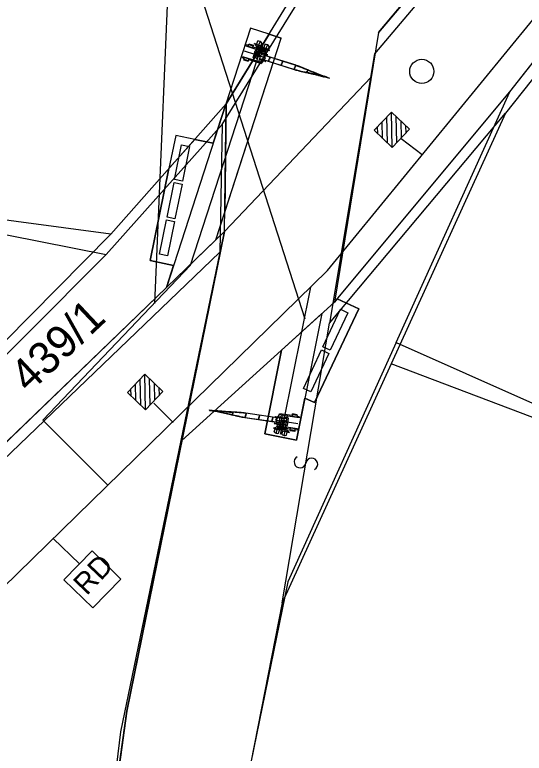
# Model space of a CAD drawing. Extents: x -678683 to -677755, y -1006946 to -1005971.
# Drawn here: x -678295.9 to -678264.31, y -1006533.89 to -1006488.07 of the extents above; entities that cross this region are included whole.
import ezdxf

# ---------------------------------------------------------------- set-up
doc = ezdxf.new("R2010")
doc.units = 0
for name, color, linetype in [('Default', 7, 'Continuous'), ('I_2_4_předběžný_vykres - Dočasný zábor - do 1 roku', 7, 'Continuous'), ('I_2_4_předběžný_vykres - Dočasný zábor - do 1 roku - ZPF', 7, 'Continuous'), ('I_2_4_předběžný_vykres - SŽDC', 7, 'Continuous'), ('I_2_4_předběžný_vykres - Trvalý zábor', 7, 'Continuous'), ('I_2_4_předběžný_vykres - VBř', 7, 'Continuous'), ('kilometráž - Vrstva 7', 7, 'Continuous'), ('koor - OSY', 7, 'Continuous'), ('koor - SSZT_nové', 7, 'Continuous'), ('MapaKN - Mladejov+Strelec_dosavani+nova_situace - Vrstva 11', 7, 'Continuous'), ('MapaKN - Mladejov+Strelec_dosavani+nova_situace - Vrstva 18', 7, 'Continuous'), ('MapaKN - původní vrstava 1', 7, 'Continuous'), ('popis', 7, 'Continuous')]:
    doc.layers.add(name, color=color, linetype=linetype)

# ---------------------------------------------------------------- blocks, each defined once
blk = doc.blocks.new('AZD97_VYSTRAZNIK')
at = {"layer": 'Default'}
for p, q in [((-34, -7.5), (-24, 8)), ((-24, 8), (0, 8)), ((-20, 2), (0, 2)), ((24, 8), (0, 8)), ((20, 2), (0, 2)), ((34, -7.5), (24, 8)), ((0, -7.5), (-40, -7.5)), ((-40, -7.5), (-40, -8)), ((0, -8), (-40, -8)), ((-36.9, -7.5), (-36.9, -3)), ((-36.9, -3), (-31.1, -3)), ((-34, -8), (-34, -9.5)), ((-34, -9.5), (-20, -9.5)), ((-31.5, -25.2), (-31.5, -9.5)), ((-20, -2), (0, -2)), ((-6, -9.5), (-20, -9.5)), ((-8.5, -25.2), (-8.5, -9.5)), ((-6, -8), (-6, -9.5)), ((20, -2), (0, -2)), ((0, -7.5), (40, -7.5)), ((0, -8), (40, -8)), ((6, -8), (6, -9.5)), ((6, -9.5), (20, -9.5)), ((8.5, -25.2), (8.5, -9.5)), ((34, -9.5), (20, -9.5)), ((36.9, -3), (31.1, -3)), ((31.5, -25.2), (31.5, -9.5)), ((34, -8), (34, -9.5)), ((36.9, -7.5), (36.9, -3)), ((40, -7.5), (40, -8))]:
    blk.add_line(p, q, dxfattribs=at)
for centre in [(-20, 0), (20, 0)]:
    blk.add_circle(centre, 2, dxfattribs=at)
for centre, start, end in [((-20, -9.5), 233.8612, 270), ((-20, -9.5), 270, 306.1388), ((20, -9.5), 233.8612, 270), ((20, -9.5), 270, 306.1388)]:
    blk.add_arc(centre, 19.5, start, end, dxfattribs=at)
at = {"layer": 'koor - OSY'}
for p, q in [((-24.8, 0), (25.7, 0)), ((-20, -29), (-20, 8)), ((0, 8), (0, -29.7)), ((20, -29), (20, 8))]:
    blk.add_line(p, q, dxfattribs=at)
blk = doc.blocks.new('AZD97_DRZAK')
at = {"layer": 'Default'}
for p, q in [((-4, -5.3), (-4, -38.3)), ((-0.7, -7.4), (-0.7, -6.6)), ((0.6, -7.4), (0.6, -6.6)), ((4, -5.3), (4, -38.3))]:
    blk.add_line(p, q, dxfattribs=at)
for centre, radius, start, end in [((0, 0), 6.65, 233.0223, 306.9777), ((0, 0), 7.5, 237.769, 270), ((0, 0), 7.5, 270, 302.231), ((0, -38.3), 4, 180, 0)]:
    blk.add_arc(centre, radius, start, end, dxfattribs=at)
at = {"layer": 'koor - OSY'}
for p, q in [((0, 6.6), (0, -42.3)), ((-6.7, 0), (6.6, 0)), ((-4, -38.3), (4, -38.3))]:
    blk.add_line(p, q, dxfattribs=at)
blk = doc.blocks.new('AZD99_KŘÍDLA')
at = {"layer": 'Default'}
for p, q in [((47, 47.5), (47, 52.5)), ((77, 52.5), (47, 52.5)), ((77, 47.5), (47, 47.5)), ((47, 47.5), (47, 36.5)), ((77, 47.5), (77, 52.5)), ((77, 47.5), (77, 36.5)), ((-56, 22), (-16, 22)), ((-56, 22), (-56, 20)), ((-56, 20), (-16, 20)), ((-46, 0), (-34, 42)), ((-46, 0), (-34, -42)), ((91, 34.5), (-36.2, 34.5)), ((47, 42), (-34, 42)), ((-16, 42), (-16, 0)), ((-16, -42), (-16, 0)), ((77, 36.5), (47, 36.5)), ((91, 42), (77, 42)), ((91, 42), (91, 34.5)), ((-56, -20), (-16, -20)), ((-56, -22), (-56, -20)), ((-56, -22), (-16, -22)), ((91, -34.5), (-36.2, -34.5)), ((47, -42), (-34, -42)), ((77, -36.5), (47, -36.5)), ((47, -47.5), (47, -36.5)), ((77, -47.5), (77, -36.5)), ((91, -42), (77, -42)), ((91, -42), (91, -34.5)), ((77, -47.5), (47, -47.5)), ((47, -47.5), (47, -52.5)), ((77, -52.5), (47, -52.5)), ((77, -47.5), (77, -52.5))]:
    blk.add_line(p, q, dxfattribs=at)
at = {"layer": 'koor - OSY'}
for p, q in [((-46, 0), (89, 0)), ((0, 21.9), (0, -22.2)), ((16, 42), (16, -42))]:
    blk.add_line(p, q, dxfattribs=at)

msp = doc.modelspace()

# ---------------------------------------------------------------- linework, layer by layer
at = {"layer": 'I_2_4_předběžný_vykres - Dočasný zábor - do 1 roku'}
for p, q in [((-678280.139, -1006489.272), (-678282.79, -1006493.59)), ((-678279.381, -1006489.517), (-678280.139, -1006489.272)), ((-678283.435, -1006502.026), (-678279.381, -1006489.517)), ((-678282.884, -1006500.325), (-678279.381, -1006489.517)), ((-678282.811, -1006493.613), (-678283.595, -1006496.033)), ((-678282.79, -1006493.59), (-678282.884, -1006500.325)), ((-678282.884, -1006500.325), (-678282.79, -1006493.59)), ((-678282.79, -1006493.59), (-678282.811, -1006493.613)), ((-678284.743, -1006495.797), (-678286.341, -1006497.603)), ((-678283.595, -1006496.033), (-678284.743, -1006495.797)), ((-678283.435, -1006502.026), (-678282.884, -1006500.325)), ((-678286.495, -1006504.981), (-678283.435, -1006502.026)), ((-678286.053, -1006503.616), (-678286.495, -1006504.981)), ((-678276.08, -1006505.89), (-678279.356, -1006508.868)), ((-678275.913, -1006505.69), (-678276.08, -1006505.89)), ((-678278.442, -1006514.466), (-678277.916, -1006511.854)), ((-678278.442, -1006514.466), (-678277.916, -1006511.854)), ((-678277.916, -1006511.854), (-678277.328, -1006512.133))]:
    msp.add_line(p, q, dxfattribs=at)
for points in [[(-678280.139, -1006489.272), (-678279.381, -1006489.517)], [(-678283.595, -1006496.033), (-678282.811, -1006493.613)], [(-678284.743, -1006495.797), (-678283.595, -1006496.033)], [(-678286.053, -1006503.616), (-678287.515, -1006503.316), (-678286.341, -1006497.603)], [(-678286.341, -1006497.603), (-678287.515, -1006503.316), (-678286.053, -1006503.616)], [(-678286.495, -1006504.981), (-678286.053, -1006503.616)], [(-678275.913, -1006505.69), (-678274.577, -1006506.322), (-678277.328, -1006512.133)], [(-678277.328, -1006512.133), (-678274.577, -1006506.322), (-678275.913, -1006505.69)], [(-678278.442, -1006514.466), (-678280.402, -1006514.072), (-678279.356, -1006508.868)], [(-678279.356, -1006508.868), (-678280.402, -1006514.072), (-678278.442, -1006514.466)], [(-678277.328, -1006512.133), (-678277.916, -1006511.854)]]:
    msp.add_lwpolyline(points, dxfattribs=at)
at = {"layer": 'I_2_4_předběžný_vykres - Dočasný zábor - do 1 roku - ZPF'}
for points in [[(-678280.139, -1006489.272), (-678281.283, -1006488.901), (-678282.811, -1006493.613), (-678282.79, -1006493.59)], [(-678286.341, -1006497.603), (-678284.743, -1006495.797), (-678285.921, -1006495.555)]]:
    msp.add_lwpolyline(points, close=True, dxfattribs=at)
at = {"layer": 'I_2_4_předběžný_vykres - SŽDC'}
for p, q in [((-678265.21, -1006492.84), (-678232.55, -1006451.35)), ((-678259.32, -1006472.44), (-678273.34, -1006489.17)), ((-678273.34, -1006489.17), (-678276.08, -1006505.89)), ((-678276.08, -1006505.89), (-678265.21, -1006492.84)), ((-678285.543, -1006514.493), (-678282.9, -1006501.51)), ((-678282.9, -1006501.51), (-678283.435, -1006502.026)), ((-678283.435, -1006502.026), (-678286.495, -1006504.981)), ((-678286.495, -1006504.981), (-678297.37, -1006515.48)), ((-678288.96, -1006531.28), (-678285.543, -1006514.493)), ((-678290.92, -1006545.55), (-678288.96, -1006531.28))]:
    msp.add_line(p, q, dxfattribs=at)
at = {"layer": 'I_2_4_předběžný_vykres - Trvalý zábor'}
msp.add_lwpolyline([(-678282.9, -1006501.51), (-678273.795, -1006491.947), (-678276.08, -1006505.89), (-678285.543, -1006514.493)], dxfattribs=at)
msp.add_lwpolyline([(-678282.9, -1006501.51), (-678273.795, -1006491.947), (-678276.08, -1006505.89), (-678285.543, -1006514.493)], close=True, dxfattribs=at)
at = {"layer": 'I_2_4_předběžný_vykres - VBř'}
for points in [[(-678283.435, -1006502.026), (-678279.381, -1006489.517), (-678280.139, -1006489.272), (-678282.811, -1006493.613), (-678286.495, -1006504.981)], [(-678276.859, -1006506.598), (-678278.442, -1006514.466), (-678280.402, -1006514.072), (-678279.356, -1006508.868)]]:
    msp.add_lwpolyline(points, close=True, dxfattribs=at)
at = {"layer": 'kilometráž - Vrstva 7'}
msp.add_circle((-678270.665, -1006491.581), 0.75, dxfattribs=at)
at = {"layer": 'koor - SSZT_nové'}
for p, q in [((-678285, -1006503.611), (-678280.64, -1006490.16)), ((-678281.125, -1006490.734), (-678280.987, -1006490.305)), ((-678280.956, -1006490.289), (-678280.754, -1006490.354)), ((-678280.754, -1006490.354), (-678280.527, -1006490.426)), ((-678281.014, -1006490.717), (-678280.907, -1006490.383)), ((-678281.014, -1006490.717), (-678280.871, -1006490.762)), ((-678280.907, -1006490.383), (-678280.764, -1006490.429)), ((-678280.622, -1006490.475), (-678280.764, -1006490.429)), ((-678280.713, -1006490.79), (-678278.571, -1006491.471)), ((-678280.709, -1006490.777), (-678278.566, -1006491.457)), ((-678280.593, -1006490.421), (-678280.666, -1006490.645)), ((-678280.619, -1006490.502), (-678280.666, -1006490.646)), ((-678280.623, -1006490.515), (-678278.481, -1006491.196)), ((-678280.619, -1006490.502), (-678278.477, -1006491.183)), ((-678280.371, -1006490.492), (-678280.593, -1006490.421)), ((-678280.181, -1006490.944), (-678280.139, -1006490.814)), ((-678280.159, -1006490.951), (-678280.117, -1006490.821)), ((-678280.096, -1006490.683), (-678280.139, -1006490.814)), ((-678280.074, -1006490.69), (-678280.117, -1006490.821)), ((-678279.385, -1006491.197), (-678279.342, -1006491.067)), ((-678279.363, -1006491.204), (-678279.32, -1006491.074)), ((-678279.3, -1006490.936), (-678279.342, -1006491.067)), ((-678279.278, -1006490.943), (-678279.32, -1006491.074)), ((-678278.503, -1006491.189), (-678278.546, -1006491.32)), ((-678278.481, -1006491.196), (-678278.524, -1006491.327)), ((-678278.588, -1006491.451), (-678278.546, -1006491.32)), ((-678278.566, -1006491.457), (-678278.524, -1006491.327)), ((-678277.803, -1006491.644), (-678277.777, -1006491.564)), ((-678277.78, -1006491.649), (-678277.755, -1006491.571)), ((-678277.751, -1006491.484), (-678277.777, -1006491.564)), ((-678277.729, -1006491.493), (-678277.755, -1006491.571)), ((-678277.014, -1006491.829), (-678277.008, -1006491.808)), ((-678277.001, -1006491.788), (-678277.008, -1006491.808)), ((-678276.992, -1006491.834), (-678276.986, -1006491.815)), ((-678276.979, -1006491.796), (-678276.986, -1006491.815)), ((-678276.366, -1006492.017), (-678276.717, -1006491.922)), ((-678276.366, -1006492.017), (-678276.705, -1006491.883)), ((-678272.793, -1006496.019), (-678272.837, -1006494.402)), ((-678272.494, -1006496.303), (-678272.553, -1006494.103)), ((-678272.21, -1006496.003), (-678272.254, -1006494.386)), ((-678273.093, -1006495.735), (-678273.121, -1006494.702)), ((-678271.926, -1006495.703), (-678271.954, -1006494.671)), ((-678271.643, -1006495.404), (-678271.655, -1006494.954)), ((-678273.392, -1006495.451), (-678273.405, -1006495.002)), ((-678271.945, -1006495.744), (-678270.648, -1006496.728)), ((-678285, -1006503.611), (-678294.158, -1006513.226)), ((-678279.225, -1006513.289), (-678277.553, -1006504.979)), ((-678287.788, -1006512.573), (-678287.848, -1006510.373)), ((-678288.388, -1006512.005), (-678288.416, -1006510.973)), ((-678288.088, -1006512.289), (-678288.132, -1006510.673)), ((-678287.505, -1006512.273), (-678287.549, -1006510.657)), ((-678287.221, -1006511.974), (-678287.249, -1006510.941)), ((-678288.687, -1006511.722), (-678288.699, -1006511.272)), ((-678286.937, -1006511.674), (-678286.949, -1006511.224)), ((-678287.288, -1006512.164), (-678286.073, -1006513.373)), ((-678283.83, -1006512.608), (-678283.832, -1006512.621)), ((-678283.832, -1006512.621), (-678283.49, -1006512.672)), ((-678283.828, -1006512.594), (-678283.826, -1006512.581)), ((-678283.826, -1006512.581), (-678283.484, -1006512.632)), ((-678283.205, -1006512.714), (-678283.202, -1006512.694)), ((-678283.199, -1006512.674), (-678283.202, -1006512.694)), ((-678283.182, -1006512.718), (-678283.179, -1006512.698)), ((-678283.176, -1006512.677), (-678283.179, -1006512.698)), ((-678282.416, -1006512.894), (-678282.404, -1006512.813)), ((-678282.391, -1006512.732), (-678282.404, -1006512.813)), ((-678282.394, -1006512.899), (-678282.381, -1006512.816)), ((-678282.368, -1006512.733), (-678282.381, -1006512.816)), ((-678281.584, -1006512.795), (-678281.605, -1006512.931)), ((-678279.361, -1006513.126), (-678281.584, -1006512.795)), ((-678281.562, -1006512.799), (-678281.583, -1006512.935)), ((-678279.359, -1006513.112), (-678281.582, -1006512.782)), ((-678294.158, -1006513.226), (-678290.107, -1006517.269)), ((-678279.405, -1006513.411), (-678281.629, -1006513.081)), ((-678281.627, -1006513.067), (-678281.605, -1006512.931)), ((-678279.403, -1006513.397), (-678281.627, -1006513.067)), ((-678281.604, -1006513.071), (-678281.583, -1006512.935)), ((-678280.8, -1006513.19), (-678280.779, -1006513.054)), ((-678280.758, -1006512.918), (-678280.779, -1006513.054)), ((-678280.777, -1006513.193), (-678280.756, -1006513.057)), ((-678280.735, -1006512.922), (-678280.756, -1006513.057)), ((-678279.973, -1006513.313), (-678279.952, -1006513.177)), ((-678279.931, -1006513.041), (-678279.952, -1006513.177)), ((-678279.951, -1006513.316), (-678279.929, -1006513.18)), ((-678279.908, -1006513.044), (-678279.929, -1006513.18)), ((-678279.724, -1006513.211), (-678279.575, -1006512.994)), ((-678279.724, -1006513.211), (-678279.648, -1006513.461)), ((-678279.575, -1006512.994), (-678279.346, -1006513.028)), ((-678279.505, -1006513.472), (-678279.438, -1006513.027)), ((-678279.418, -1006513.495), (-678279.382, -1006513.262)), ((-678279.409, -1006513.006), (-678279.174, -1006513.042)), ((-678279.405, -1006513.411), (-678279.382, -1006513.262)), ((-678279.346, -1006513.092), (-678279.398, -1006513.438)), ((-678279.346, -1006513.028), (-678279.382, -1006513.261)), ((-678279.359, -1006513.112), (-678279.382, -1006513.262)), ((-678279.346, -1006513.092), (-678279.198, -1006513.114)), ((-678279.05, -1006513.136), (-678279.198, -1006513.114)), ((-678279.174, -1006513.042), (-678278.964, -1006513.073)), ((-678279.05, -1006513.136), (-678279.102, -1006513.482)), ((-678278.943, -1006513.102), (-678279.01, -1006513.547)), ((-678279.648, -1006513.461), (-678279.418, -1006513.495)), ((-678279.249, -1006513.536), (-678279.484, -1006513.501)), ((-678279.398, -1006513.438), (-678279.25, -1006513.46)), ((-678279.102, -1006513.482), (-678279.25, -1006513.46)), ((-678279.039, -1006513.568), (-678279.249, -1006513.536)), ((-678291.888, -1006522.135), (-678293.53, -1006520.566))]:
    msp.add_line(p, q, dxfattribs=at)
for points in [[(-678276.518, -1006503.932), (-678257.417, -1006480.575), (-678238.833, -1006456.747), (-678223.794, -1006437.464), (-678213.311, -1006424.022), (-678199.433, -1006408.271)], [(-678506.624, -1006791.938), (-678466.12, -1006753.227), (-678449.329, -1006728.75), (-678428.753, -1006695.612), (-678421.07, -1006681.971), (-678401.666, -1006635.236), (-678393.87, -1006623.108), (-678390.132, -1006617.261), (-678380.001, -1006603.755), (-678359.836, -1006584.701), (-678339.66, -1006565.68), (-678276.518, -1006503.932), (-678276.518, -1006503.932)]]:
    msp.add_lwpolyline(points, dxfattribs=at)
for points in [[(-678273.623, -1006495.233), (-678272.553, -1006494.103), (-678271.424, -1006495.173), (-678272.494, -1006496.303)], [(-678285.555, -1006496.141), (-678285.061, -1006496.242), (-678285.501, -1006498.384), (-678285.995, -1006498.282)], [(-678286.022, -1006498.481), (-678285.528, -1006498.583), (-678285.968, -1006500.724), (-678286.462, -1006500.623)], [(-678286.485, -1006500.785), (-678285.991, -1006500.887), (-678286.431, -1006503.028), (-678286.925, -1006502.927)], [(-678275.699, -1006506.344), (-678275.243, -1006506.56), (-678276.345, -1006508.888), (-678276.8, -1006508.672)], [(-678276.878, -1006508.866), (-678276.422, -1006509.082), (-678277.554, -1006511.472), (-678278.009, -1006511.257)], [(-678288.918, -1006511.503), (-678287.848, -1006510.373), (-678286.718, -1006511.443), (-678287.788, -1006512.573)], [(-678292.854, -1006523.132), (-678291.113, -1006521.338), (-678289.318, -1006523.079), (-678291.059, -1006524.873)]]:
    msp.add_lwpolyline(points, close=True, dxfattribs=at)
for centre in [(-678280.818, -1006490.596), (-678279.224, -1006513.287)]:
    msp.add_circle(centre, 0.0831, dxfattribs=at)
for centre, start, end in [((-678280.964, -1006490.313), 72.2544, 162.2544), ((-678281.101, -1006490.741), 162.2544, 252.2544), ((-678280.535, -1006490.45), 342.2544, 72.2544), ((-678279.413, -1006513.031), 81.4339, 171.4339), ((-678278.968, -1006513.098), 351.4339, 81.4339), ((-678279.48, -1006513.476), 171.4339, 261.4339), ((-678279.035, -1006513.543), 261.4339, 351.4339)]:
    msp.add_arc(centre, 0.025, start, end, dxfattribs=at)
for points in [[(-678278.481, -1006491.197), (-678278.126, -1006491.331), (-678277.477, -1006491.599), (-678277.001, -1006491.788), (-678276.709, -1006491.896), (-678278.481, -1006491.197), (-678276.709, -1006491.896)], [(-678278.476, -1006491.185), (-678278.395, -1006491.214), (-678278.314, -1006491.244), (-678278.191, -1006491.291), (-678278.15, -1006491.307), (-678278.068, -1006491.339), (-678278.027, -1006491.355), (-678277.904, -1006491.405), (-678277.822, -1006491.439), (-678277.671, -1006491.503), (-678277.601, -1006491.532), (-678277.455, -1006491.593), (-678277.38, -1006491.624), (-678277.229, -1006491.685), (-678277.154, -1006491.715), (-678277.033, -1006491.761), (-678276.989, -1006491.778), (-678276.899, -1006491.812), (-678276.854, -1006491.829), (-678276.774, -1006491.858), (-678276.738, -1006491.871), (-678276.703, -1006491.884)], [(-678278.568, -1006491.47), (-678278.485, -1006491.492), (-678278.402, -1006491.515), (-678278.275, -1006491.547), (-678278.232, -1006491.558), (-678278.146, -1006491.58), (-678278.103, -1006491.59), (-678277.974, -1006491.62), (-678277.888, -1006491.639), (-678277.727, -1006491.675), (-678277.652, -1006491.691), (-678277.499, -1006491.726), (-678277.419, -1006491.744), (-678277.261, -1006491.781), (-678277.182, -1006491.8), (-678277.056, -1006491.832), (-678277.01, -1006491.844), (-678276.917, -1006491.868), (-678276.871, -1006491.881), (-678276.788, -1006491.903), (-678276.752, -1006491.913), (-678276.716, -1006491.923)], [(-678278.566, -1006491.457), (-678278.198, -1006491.553), (-678277.512, -1006491.709), (-678277.014, -1006491.829), (-678276.713, -1006491.909), (-678278.566, -1006491.457), (-678276.713, -1006491.909)], [(-678281.63, -1006513.079), (-678281.715, -1006513.063), (-678281.8, -1006513.046), (-678281.928, -1006513.02), (-678281.971, -1006513.011), (-678282.058, -1006512.992), (-678282.101, -1006512.982), (-678282.23, -1006512.953), (-678282.316, -1006512.932), (-678282.476, -1006512.894), (-678282.55, -1006512.876), (-678282.703, -1006512.839), (-678282.782, -1006512.82), (-678282.94, -1006512.784), (-678283.02, -1006512.767), (-678283.146, -1006512.74), (-678283.193, -1006512.73), (-678283.287, -1006512.711), (-678283.334, -1006512.702), (-678283.418, -1006512.686), (-678283.455, -1006512.679), (-678283.492, -1006512.672)], [(-678281.626, -1006513.066), (-678281.999, -1006512.991), (-678282.682, -1006512.83), (-678283.182, -1006512.718), (-678283.488, -1006512.659), (-678281.626, -1006513.066), (-678283.488, -1006512.659)], [(-678281.584, -1006512.796), (-678281.963, -1006512.76), (-678282.665, -1006512.715), (-678283.176, -1006512.677), (-678283.486, -1006512.645), (-678281.584, -1006512.796), (-678283.486, -1006512.645)], [(-678281.584, -1006512.783), (-678281.67, -1006512.774), (-678281.756, -1006512.765), (-678281.886, -1006512.753), (-678281.93, -1006512.749), (-678282.019, -1006512.742), (-678282.063, -1006512.739), (-678282.195, -1006512.729), (-678282.283, -1006512.724), (-678282.448, -1006512.714), (-678282.524, -1006512.71), (-678282.681, -1006512.701), (-678282.762, -1006512.696), (-678282.925, -1006512.684), (-678283.006, -1006512.678), (-678283.135, -1006512.667), (-678283.182, -1006512.662), (-678283.278, -1006512.653), (-678283.326, -1006512.648), (-678283.411, -1006512.639), (-678283.448, -1006512.635), (-678283.485, -1006512.631)]]:
    msp.add_open_spline(points, degree=3, dxfattribs=at)
at = {"layer": 'MapaKN - Mladejov+Strelec_dosavani+nova_situace - Vrstva 11'}
for points in [[(-678265.21, -1006492.84), (-678232.55, -1006451.35)], [(-678273.34, -1006489.17), (-678259.32, -1006472.44)], [(-678282.79, -1006493.59), (-678272.96, -1006477.58)], [(-678273.34, -1006489.17), (-678276.08, -1006505.89)], [(-678276.08, -1006505.89), (-678265.21, -1006492.84)], [(-678272.25, -1006508.4), (-678265.21, -1006492.84)], [(-678282.79, -1006493.59), (-678289.95, -1006501.68)], [(-678282.9, -1006501.51), (-678282.79, -1006493.59)], [(-678289.95, -1006501.68), (-678310.51, -1006498.93)], [(-678299.87, -1006511.71), (-678289.95, -1006501.68)], [(-678297.37, -1006515.48), (-678282.9, -1006501.51)], [(-678282.9, -1006501.51), (-678288.96, -1006531.28)], [(-678272.25, -1006508.4), (-678278.97, -1006523.26)], [(-678272.25, -1006508.4), (-678250.47, -1006518.1)], [(-678278.97, -1006523.26), (-678281.26, -1006534.47)], [(-678288.96, -1006531.28), (-678290.92, -1006545.55)]]:
    msp.add_lwpolyline(points, dxfattribs=at)
at = {"layer": 'MapaKN - původní vrstava 1'}
for points in [[(-678232.67, -1006452.8), (-678265.47, -1006494.18)], [(-678259.51, -1006473.8), (-678273.59, -1006490.49)], [(-678283.05, -1006494.88), (-678273.17, -1006478.9)], [(-678273.59, -1006490.49), (-678276.38, -1006507.2)], [(-678276.38, -1006507.2), (-678265.47, -1006494.18)], [(-678265.47, -1006494.18), (-678272.56, -1006509.72)], [(-678290.24, -1006502.94), (-678283.05, -1006494.88)], [(-678283.05, -1006494.88), (-678283.19, -1006502.8)], [(-678310.51, -1006498.93), (-678290.24, -1006502.94)], [(-678290.24, -1006502.94), (-678300.19, -1006512.94)], [(-678283.19, -1006502.8), (-678297.7, -1006516.72)], [(-678283.19, -1006502.8), (-678289.35, -1006532.55)], [(-678279.33, -1006524.56), (-678276.38, -1006507.2)], [(-678272.56, -1006509.72), (-678279.33, -1006524.56)], [(-678250.47, -1006518.1), (-678272.56, -1006509.72)], [(-678279.33, -1006524.56), (-678281.26, -1006534.47)], [(-678289.35, -1006532.55), (-678290.92, -1006545.55)]]:
    msp.add_lwpolyline(points, dxfattribs=at)
for centre, start, end in [((-678278.212, -1006515.815), 118.046, 349.8233), ((-678277.488, -1006515.947), 297.6812, 169.9093)]:
    msp.add_arc(centre, 0.368, start, end, dxfattribs=at)
at = {"layer": 'popis'}
msp.add_lwpolyline([(-678277.903, -1006506.955), (-678286.191, -1006481.145), (-678287.233, -1006505.993)], dxfattribs=at)

# ---------------------------------------------------------------- block references
at = {"layer": 'koor - SSZT_nové'}
for name, p, xscale, yscale, rotation in [('AZD99_KŘÍDLA', (-678280.818, -1006490.596), 0.010000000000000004, 0.010000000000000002, 162.25443298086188), ('AZD97_VYSTRAZNIK', (-678280.614, -1006490.156), 0.012499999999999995, 0.012499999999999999, 155.69273437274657), ('AZD97_DRZAK', (-678280.817, -1006490.594), 0.012499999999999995, 0.012499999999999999, 155.41189516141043), ('AZD99_KŘÍDLA', (-678279.224, -1006513.287), 0.010000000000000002, 0.010000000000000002, -8.566093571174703), ('AZD97_DRZAK', (-678279.225, -1006513.289), 0.012499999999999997, 0.012499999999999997, -15.408631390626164), ('AZD97_VYSTRAZNIK', (-678279.355, -1006513.753), 0.012499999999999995, 0.012499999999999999, -15.127792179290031)]:
    msp.add_blockref(name, p, dxfattribs=dict(at, xscale=xscale, yscale=yscale, rotation=rotation))

# ---------------------------------------------------------------- texts
msp.add_text('RD', height=1.306, rotation=46.3725, dxfattribs=at).set_placement((-678291.446, -1006524.144))
at = {"layer": 'MapaKN - Mladejov+Strelec_dosavani+nova_situace - Vrstva 18'}
msp.add_text('439/1', height=2, rotation=43.3003, dxfattribs=at).set_placement((-678295.022, -1006511.598))

doc.saveas('drawing.dxf')
